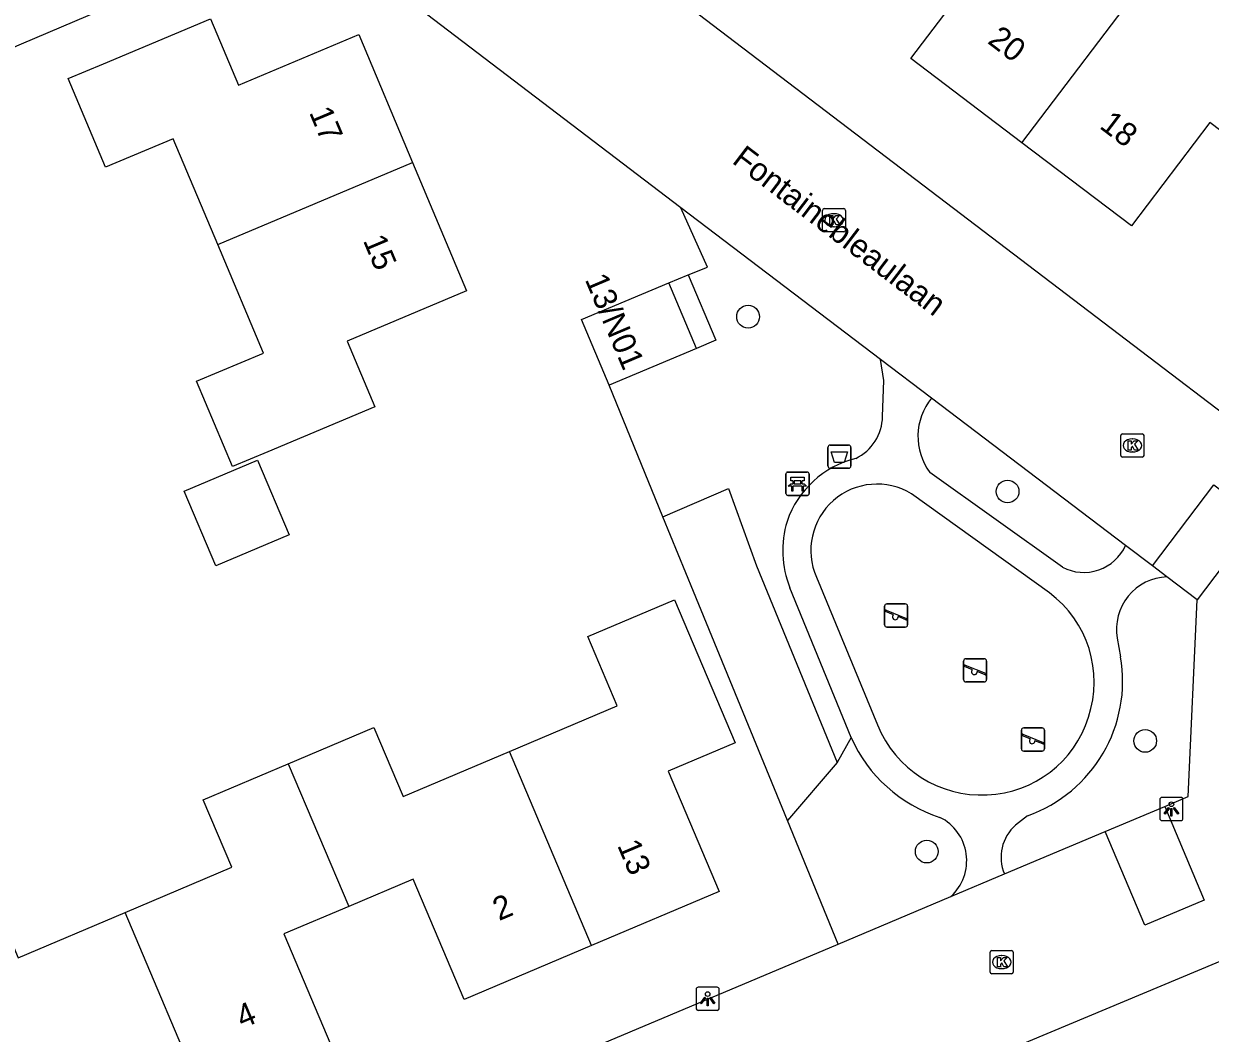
# Model space of a CAD drawing. Extents: x 158474 to 159560, y 388525 to 389605.
# Drawn here: x 158604 to 158655.1, y 389050.1 to 389093.6 of the extents above; entities that cross this region are included whole.
import ezdxf

# ---------------------------------------------------------------- set-up
doc = ezdxf.new("R2010")
doc.units = 0
for name, color, linetype in [('IMGEO_Afvalbak', 7, 'Continuous'), ('IMGEO_Bank', 7, 'Continuous'), ('IMGEO_Boom', 7, 'Continuous'), ('IMGEO_Groenvoorziening', 7, 'Continuous'), ('IMGEO_Kolk', 7, 'Continuous'), ('IMGEO_Lichtpunt', 7, 'Continuous'), ('IMGEO_Openbare_ruimte_label', 7, 'Continuous'), ('IMGEO_Pand', 7, 'Continuous'), ('IMGEO_Pand_nummerreeks', 7, 'Continuous'), ('IMGEO_Rijbaan_lokaal_open', 7, 'Continuous'), ('IMGEO_Speelvoorziening', 7, 'Continuous'), ('IMGEO_Voetpad_open', 7, 'Continuous')]:
    doc.layers.add(name, color=color, linetype=linetype)

msp = doc.modelspace()

# ---------------------------------------------------------------- linework, layer by layer
at = {"layer": 'IMGEO_Afvalbak'}
for p, q in [((158638.613, 389074.52), (158638.613, 389075.32)), ((158638.613, 389075.32), (158638.613, 389074.52)), ((158638.713, 389075.42), (158639.503, 389075.42)), ((158639.503, 389075.42), (158638.713, 389075.42)), ((158639.603, 389075.32), (158639.603, 389074.52)), ((158639.603, 389074.52), (158639.603, 389075.32)), ((158639.503, 389074.42), (158638.713, 389074.42)), ((158638.713, 389074.42), (158639.503, 389074.42))]:
    msp.add_line(p, q, dxfattribs=at)
msp.add_lwpolyline([(158638.756, 389075.134), (158639.46, 389075.134), (158639.311, 389074.664), (158638.905, 389074.664), (158638.756, 389075.134)], dxfattribs=at)
for centre, start, end in [((158638.713, 389075.32), 90, 180), ((158638.713, 389075.32), 90, 180), ((158639.503, 389075.32), 0, 90), ((158639.503, 389075.32), 360, 90), ((158638.713, 389074.52), 180, 270), ((158638.713, 389074.52), 180, 270), ((158639.503, 389074.52), 270, 0), ((158639.503, 389074.52), 270, 0)]:
    msp.add_arc(centre, 0.1, start, end, dxfattribs=at)
at = {"layer": 'IMGEO_Bank'}
for p, q in [((158636.806, 389073.329), (158636.806, 389074.17)), ((158636.806, 389074.17), (158636.806, 389073.329)), ((158636.881, 389074.254), (158637.722, 389074.254)), ((158637.722, 389074.254), (158636.881, 389074.254)), ((158637.806, 389074.179), (158637.806, 389073.338)), ((158637.806, 389073.338), (158637.806, 389074.179)), ((158637.503, 389073.652), (158637.11, 389073.652)), ((158637.115, 389073.76), (158637.115, 389073.866)), ((158637.159, 389073.866), (158637.159, 389073.76)), ((158637.447, 389073.872), (158637.165, 389073.872)), ((158637.165, 389073.754), (158637.447, 389073.754)), ((158637.453, 389073.76), (158637.453, 389073.866)), ((158637.497, 389073.866), (158637.497, 389073.76)), ((158637.731, 389073.254), (158636.89, 389073.254)), ((158636.89, 389073.254), (158637.731, 389073.254))]:
    msp.add_line(p, q, dxfattribs=at)
for points in [[(158637.053, 389073.652), (158636.911, 389073.652), (158637.023, 389073.754), (158637.109, 389073.754)], [(158637.109, 389073.872), (158637.023, 389073.872), (158637.023, 389074.033), (158637.586, 389074.033), (158637.586, 389073.872), (158637.503, 389073.872)], [(158637.103, 389073.645), (158637.103, 389073.438), (158637.06, 389073.438), (158637.06, 389073.645)], [(158637.503, 389073.754), (158637.586, 389073.754), (158637.698, 389073.652), (158637.559, 389073.652)], [(158637.553, 389073.645), (158637.553, 389073.438), (158637.509, 389073.438), (158637.509, 389073.645)]]:
    msp.add_lwpolyline(points, dxfattribs=at)
for centre, radius, start, end in [((158636.884, 389074.176), 0.0779, 92.4484, 184.2845), ((158636.884, 389074.176), 0.0779, 92.4484, 184.2845), ((158637.728, 389074.176), 0.0779, 2.4484, 94.2845), ((158637.728, 389074.176), 0.0779, 2.4484, 94.2845), ((158637.053, 389073.645), 0.00671, 2.8957, 87.1043), ((158637.11, 389073.645), 0.00671, 92.8957, 177.1043), ((158637.108, 389073.865), 0.00671, 2.8957, 87.1043), ((158637.108, 389073.761), 0.00671, 272.8957, 357.1043), ((158637.165, 389073.865), 0.00671, 92.8957, 177.1043), ((158637.165, 389073.761), 0.00671, 182.8957, 267.1043), ((158637.447, 389073.865), 0.00671, 2.8957, 87.1043), ((158637.447, 389073.761), 0.00671, 272.8957, 357.1043), ((158637.504, 389073.865), 0.00671, 92.8957, 177.1043), ((158637.504, 389073.761), 0.00671, 182.8957, 267.1043), ((158637.502, 389073.645), 0.00671, 2.8957, 87.1043), ((158637.559, 389073.645), 0.00671, 92.8957, 177.1043), ((158636.884, 389073.332), 0.0779, 182.4484, 274.2845), ((158636.884, 389073.332), 0.0779, 182.4484, 274.2845), ((158637.728, 389073.332), 0.0779, 272.4484, 4.2845), ((158637.728, 389073.332), 0.0779, 272.4484, 4.2845)]:
    msp.add_arc(centre, radius, start, end, dxfattribs=at)
at = {"layer": 'IMGEO_Boom'}
for centre in [(158635.178, 389080.946), (158646.351, 389073.419), (158652.276, 389062.68), (158642.87, 389057.916)]:
    msp.add_circle(centre, 0.489, dxfattribs=at)
at = {"layer": 'IMGEO_Groenvoorziening'}
for points in [[(158632.597, 389082.746), (158633.427, 389083.084), (158632.28, 389085.631)], [(158631.513, 389072.331), (158629.191, 389077.996)], [(158639.62, 389062.825), (158639.015, 389061.757)], [(158639.056, 389053.929), (158636.872, 389059.257)]]:
    msp.add_lwpolyline(points, dxfattribs=at)
at = {"layer": 'IMGEO_Kolk'}
for p, q in [((158638.377, 389084.673), (158638.377, 389085.525)), ((158638.452, 389085.599), (158639.304, 389085.599)), ((158639.378, 389085.525), (158639.378, 389084.673)), ((158638.865, 389085.379), (158638.89, 389085.379)), ((158639.304, 389084.599), (158638.452, 389084.599)), ((158638.888, 389084.819), (158638.863, 389084.819)), ((158651.223, 389074.976), (158651.223, 389075.828)), ((158651.298, 389075.902), (158652.15, 389075.902)), ((158651.711, 389075.682), (158651.736, 389075.682)), ((158652.224, 389075.828), (158652.224, 389074.976)), ((158652.15, 389074.902), (158651.298, 389074.902)), ((158651.734, 389075.122), (158651.709, 389075.122)), ((158645.597, 389052.73), (158645.597, 389053.582)), ((158645.672, 389053.656), (158646.524, 389053.656)), ((158646.085, 389053.436), (158646.11, 389053.436)), ((158646.598, 389053.582), (158646.598, 389052.73)), ((158646.108, 389052.876), (158646.083, 389052.876)), ((158646.524, 389052.656), (158645.672, 389052.656))]:
    msp.add_line(p, q, dxfattribs=at)
for points in [[(158638.377, 389084.673), (158638.377, 389085.525)], [(158638.452, 389085.599), (158639.304, 389085.599)], [(158639.378, 389085.525), (158639.378, 389084.673)], [(158638.698, 389085.299), (158638.821, 389085.299), (158638.821, 389085.148), (158638.951, 389085.299), (158639.115, 389085.299), (158638.969, 389085.148), (158639.122, 389084.899), (158638.97, 389084.899), (158638.885, 389085.063), (158638.821, 389084.996), (158638.821, 389084.899), (158638.698, 389084.899), (158638.698, 389085.299)], [(158639.304, 389084.599), (158638.452, 389084.599)], [(158651.223, 389074.976), (158651.223, 389075.828)], [(158651.298, 389075.902), (158652.15, 389075.902)], [(158652.224, 389075.828), (158652.224, 389074.976)], [(158651.544, 389075.602), (158651.667, 389075.602), (158651.667, 389075.451), (158651.797, 389075.602), (158651.961, 389075.602), (158651.815, 389075.451), (158651.968, 389075.202), (158651.816, 389075.202), (158651.731, 389075.366), (158651.667, 389075.299), (158651.667, 389075.202), (158651.544, 389075.202), (158651.544, 389075.602)], [(158652.15, 389074.902), (158651.298, 389074.902)], [(158645.597, 389052.73), (158645.597, 389053.582)], [(158645.672, 389053.656), (158646.524, 389053.656)], [(158645.918, 389053.356), (158646.041, 389053.356), (158646.041, 389053.205), (158646.171, 389053.356), (158646.335, 389053.356), (158646.189, 389053.205), (158646.342, 389052.956), (158646.19, 389052.956), (158646.105, 389053.12), (158646.041, 389053.053), (158646.041, 389052.956), (158645.918, 389052.956), (158645.918, 389053.356)], [(158646.598, 389053.582), (158646.598, 389052.73)], [(158646.524, 389052.656), (158645.672, 389052.656)]]:
    msp.add_lwpolyline(points, dxfattribs=at)
for centre, start, end in [((158638.454, 389085.523), 91.552, 178.448), ((158638.454, 389085.523), 91.552, 178.448), ((158639.302, 389085.523), 1.552, 88.448), ((158639.302, 389085.523), 1.552, 88.448), ((158638.454, 389084.675), 181.552, 268.448), ((158638.454, 389084.675), 181.552, 268.448), ((158639.302, 389084.675), 271.552, 358.448), ((158639.302, 389084.675), 271.552, 358.448), ((158651.3, 389075.826), 91.552, 178.448), ((158651.3, 389075.826), 91.552, 178.448), ((158652.148, 389075.826), 1.552, 88.448), ((158652.148, 389075.826), 1.552, 88.448), ((158651.3, 389074.978), 181.552, 268.448), ((158651.3, 389074.978), 181.552, 268.448), ((158652.148, 389074.978), 271.552, 358.448), ((158652.148, 389074.978), 271.552, 358.448), ((158645.674, 389053.58), 91.552, 178.448), ((158645.674, 389053.58), 91.552, 178.448), ((158646.522, 389053.58), 1.552, 88.448), ((158646.522, 389053.58), 1.552, 88.448), ((158645.674, 389052.732), 181.552, 268.448), ((158645.674, 389052.732), 181.552, 268.448), ((158646.522, 389052.732), 271.552, 358.448), ((158646.522, 389052.732), 271.552, 358.448)]:
    msp.add_arc(centre, 0.0765, start, end, dxfattribs=at)
for centre, major_axis, ratio, start_param, end_param in [((158638.864, 389085.099), (-0.387, 0.002), 0.722429, 4.712389, 7.853982), ((158638.889, 389085.099), (-0.39, 0.002), 0.717154, 1.570796, 4.712389), ((158651.71, 389075.402), (-0.387, 0.002), 0.722429, 4.712389, 7.853982), ((158651.735, 389075.402), (-0.39, 0.002), 0.717154, 1.570796, 4.712389), ((158646.084, 389053.156), (-0.387, 0.002), 0.722429, 4.712389, 7.853982), ((158646.109, 389053.156), (-0.39, 0.002), 0.717154, 1.570796, 4.712389)]:
    msp.add_ellipse(centre, major_axis=major_axis, ratio=ratio, start_param=start_param, end_param=end_param, dxfattribs=at)
at = {"layer": 'IMGEO_Lichtpunt'}
for p, q in [((158652.906, 389060.153), (158652.906, 389059.346)), ((158652.906, 389060.153), (158652.906, 389059.346)), ((158653.808, 389060.248), (158653, 389060.248)), ((158653.808, 389060.248), (158653, 389060.248)), ((158653.902, 389059.346), (158653.902, 389060.153)), ((158653.902, 389059.346), (158653.902, 389060.153)), ((158653, 389059.252), (158653.808, 389059.252)), ((158653, 389059.252), (158653.808, 389059.252)), ((158632.939, 389051.981), (158632.939, 389051.174)), ((158632.939, 389051.981), (158632.939, 389051.174)), ((158633.841, 389052.076), (158633.033, 389052.076)), ((158633.841, 389052.076), (158633.033, 389052.076)), ((158633.935, 389051.174), (158633.935, 389051.981)), ((158633.935, 389051.174), (158633.935, 389051.981)), ((158633.033, 389051.08), (158633.841, 389051.08)), ((158633.033, 389051.08), (158633.841, 389051.08))]:
    msp.add_line(p, q, dxfattribs=at)
for points in [[(158653.28, 389059.817), (158653.319, 389059.789), (158653.131, 389059.527), (158653.093, 389059.554), (158653.28, 389059.817)], [(158653.382, 389059.769), (158653.429, 389059.769), (158653.429, 389059.447), (158653.382, 389059.447), (158653.382, 389059.769)], [(158653.492, 389059.789), (158653.53, 389059.816), (158653.717, 389059.554), (158653.678, 389059.526), (158653.492, 389059.789)], [(158633.313, 389051.645), (158633.352, 389051.617), (158633.164, 389051.355), (158633.126, 389051.382), (158633.313, 389051.645)], [(158633.415, 389051.597), (158633.462, 389051.597), (158633.462, 389051.275), (158633.415, 389051.275), (158633.415, 389051.597)], [(158633.525, 389051.617), (158633.563, 389051.644), (158633.75, 389051.382), (158633.711, 389051.354), (158633.525, 389051.617)]]:
    msp.add_lwpolyline(points, dxfattribs=at)
for centre in [(158653.405, 389059.951), (158633.438, 389051.779)]:
    msp.add_circle(centre, 0.0994, dxfattribs=at)
for centre, start, end in [((158653, 389060.153), 90, 180), ((158653, 389060.153), 90, 180), ((158653.808, 389060.153), 0, 90), ((158653.808, 389060.153), 0, 90), ((158653, 389059.346), 180, 270), ((158653, 389059.346), 180, 270), ((158653.808, 389059.346), 270, 0), ((158653.808, 389059.346), 270, 360), ((158633.033, 389051.981), 90, 180), ((158633.033, 389051.981), 90, 180), ((158633.841, 389051.981), 0, 90), ((158633.841, 389051.981), 0, 90), ((158633.033, 389051.174), 180, 270), ((158633.033, 389051.174), 180, 270), ((158633.841, 389051.174), 270, 0), ((158633.841, 389051.174), 270, 360)]:
    msp.add_arc(centre, 0.0946, start, end, dxfattribs=at)
at = {"layer": 'IMGEO_Pand'}
for points in [[(158599.882, 389100.941), (158601.096, 389098.116), (158606.137, 389100.282), (158608.471, 389094.647), (158603.878, 389092.674), (158600.199, 389091.093), (158598.161, 389095.835), (158595.246, 389094.582), (158593.662, 389098.268)], [(158646.967, 389088.432), (158642.186, 389092.061), (158645.576, 389096.527), (158643.223, 389098.313)], [(158646.967, 389088.432), (158652.463, 389095.674)], [(158612.351, 389084.052), (158610.433, 389088.608), (158607.514, 389087.379), (158605.907, 389091.198), (158607.427, 389091.838), (158612.035, 389093.777), (158613.24, 389090.914), (158618.415, 389093.093), (158620.735, 389087.58)], [(158657.482, 389087.472), (158655.063, 389089.308), (158651.682, 389084.853), (158646.967, 389088.432)], [(158620.735, 389087.58), (158623.057, 389082.064), (158617.913, 389079.898), (158619.105, 389077.067), (158614.497, 389075.127), (158612.984, 389074.49), (158611.436, 389078.167), (158614.318, 389079.38), (158612.351, 389084.052)], [(158612.351, 389084.052), (158620.735, 389087.58)], [(158629.191, 389077.996), (158628.001, 389080.824), (158631.763, 389082.407)], [(158632.954, 389079.579), (158631.763, 389082.407)], [(158632.954, 389079.579), (158629.191, 389077.996)], [(158610.906, 389073.436), (158614.06, 389074.764), (158615.414, 389071.548), (158612.26, 389070.22), (158610.906, 389073.436)], [(158624.9, 389062.228), (158629.541, 389064.194), (158628.276, 389067.181), (158632.007, 389068.761), (158634.617, 389062.599), (158631.741, 389061.38), (158633.937, 389056.198), (158628.441, 389053.87)], [(158615.382, 389061.7), (158619.069, 389063.262), (158620.328, 389060.291), (158624.9, 389062.228)], [(158628.441, 389053.87), (158624.9, 389062.228)], [(158608.356, 389055.289), (158612.953, 389057.237), (158611.719, 389060.148), (158615.382, 389061.7)], [(158615.382, 389061.7), (158617.987, 389055.55)], [(158598.842, 389054.75), (158602.499, 389056.3), (158603.753, 389053.339), (158608.356, 389055.289)], [(158628.441, 389053.87), (158622.949, 389051.543), (158620.755, 389056.723), (158617.987, 389055.55)], [(158611.905, 389046.91), (158608.356, 389055.289)], [(158617.987, 389055.55), (158615.197, 389054.368), (158617.375, 389049.227), (158611.905, 389046.91)]]:
    msp.add_lwpolyline(points, dxfattribs=at)
at = {"layer": 'IMGEO_Rijbaan_lokaal_open'}
for points in [[(158601.848, 389145.539), (158600.426, 389141.831), (158604.336, 389132.54), (158605.841, 389128.964), (158616.4, 389103.871), (158618.796, 389104.84), (158666.009, 389068.886)], [(158632.28, 389085.631), (158618.202, 389096.374), (158612.964, 389094.303), (158598.129, 389129.848)], [(158640.886, 389079.099), (158632.28, 389085.631)], [(158643.071, 389077.441), (158640.886, 389079.099)], [(158651.434, 389071.094), (158643.071, 389077.441)], [(158652.585, 389070.22), (158655.228, 389073.702), (158657.155, 389072.238), (158654.513, 389068.757)], [(158652.585, 389070.22), (158651.434, 389071.094)], [(158653.212, 389069.744), (158652.585, 389070.22)], [(158654.513, 389068.757), (158653.212, 389069.744)], [(158653.115, 389059.863), (158654.128, 389060.291), (158654.513, 389068.757)], [(158650.554, 389058.782), (158653.115, 389059.863)], [(158653.115, 389059.863), (158654.819, 389055.829), (158652.258, 389054.748), (158650.554, 389058.782)], [(158693.979, 389034.415), (158691.297, 389040.872), (158689.958, 389044.098), (158688.082, 389043.319), (158668.118, 389058.458), (158641.722, 389047.425), (158602.187, 389030.899), (158601.851, 389031.612), (158596.34, 389029.317)], [(158646.219, 389056.952), (158650.554, 389058.782)], [(158643.914, 389055.983), (158646.219, 389056.952)], [(158639.056, 389053.929), (158643.914, 389055.983)], [(158594.001, 389034.936), (158639.056, 389053.929)]]:
    msp.add_lwpolyline(points, dxfattribs=at)
at = {"layer": 'IMGEO_Speelvoorziening'}
for p, q in [((158641.156, 389068.581), (158641.946, 389068.581)), ((158641.946, 389068.581), (158641.156, 389068.581)), ((158641.056, 389067.681), (158641.056, 389068.481)), ((158641.056, 389068.481), (158641.056, 389067.681)), ((158641.439, 389068.109), (158641.1, 389068.246)), ((158641.125, 389068.306), (158642.001, 389067.953)), ((158641.977, 389067.893), (158641.637, 389068.03)), ((158642.046, 389068.481), (158642.046, 389067.681)), ((158642.046, 389067.681), (158642.046, 389068.481)), ((158641.946, 389067.581), (158641.156, 389067.581)), ((158641.156, 389067.581), (158641.946, 389067.581)), ((158644.459, 389065.319), (158644.459, 389066.119)), ((158644.459, 389066.119), (158644.459, 389065.319)), ((158644.559, 389066.219), (158645.349, 389066.219)), ((158645.349, 389066.219), (158644.559, 389066.219)), ((158645.449, 389066.119), (158645.449, 389065.319)), ((158645.449, 389065.319), (158645.449, 389066.119)), ((158644.842, 389065.747), (158644.503, 389065.884)), ((158644.528, 389065.944), (158645.404, 389065.591)), ((158645.38, 389065.531), (158645.04, 389065.668)), ((158645.349, 389065.219), (158644.559, 389065.219)), ((158644.559, 389065.219), (158645.349, 389065.219)), ((158646.945, 389062.34), (158646.945, 389063.14)), ((158646.945, 389063.14), (158646.945, 389062.34)), ((158647.014, 389062.965), (158647.89, 389062.612)), ((158647.045, 389063.24), (158647.835, 389063.24)), ((158647.835, 389063.24), (158647.045, 389063.24)), ((158647.935, 389063.14), (158647.935, 389062.34)), ((158647.935, 389062.34), (158647.935, 389063.14)), ((158647.328, 389062.768), (158646.989, 389062.905)), ((158647.866, 389062.552), (158647.526, 389062.689)), ((158647.835, 389062.24), (158647.045, 389062.24)), ((158647.045, 389062.24), (158647.835, 389062.24))]:
    msp.add_line(p, q, dxfattribs=at)
for centre, radius, start, end in [((158641.156, 389068.481), 0.1, 90, 180), ((158641.156, 389068.481), 0.1, 90, 180), ((158641.946, 389068.481), 0.1, 0, 90), ((158641.946, 389068.481), 0.1, 360, 90), ((158641.113, 389068.276), 0.0327, 68.078, 248.078), ((158641.518, 389068.019), 0.12, 130.9928, 5.1632), ((158641.156, 389067.681), 0.1, 180, 270), ((158641.156, 389067.681), 0.1, 180, 270), ((158641.946, 389067.681), 0.1, 270, 0), ((158641.946, 389067.681), 0.1, 270, 0), ((158641.989, 389067.923), 0.0327, 248.078, 68.078), ((158644.559, 389066.119), 0.1, 90, 180), ((158644.559, 389066.119), 0.1, 90, 180), ((158645.349, 389066.119), 0.1, 0, 90), ((158645.349, 389066.119), 0.1, 360, 90), ((158644.516, 389065.914), 0.0327, 68.078, 248.078), ((158644.921, 389065.657), 0.12, 130.9928, 5.1632), ((158645.392, 389065.561), 0.0327, 248.078, 68.078), ((158644.559, 389065.319), 0.1, 180, 270), ((158644.559, 389065.319), 0.1, 180, 270), ((158645.349, 389065.319), 0.1, 270, 0), ((158645.349, 389065.319), 0.1, 270, 0), ((158647.045, 389063.14), 0.1, 90, 180), ((158647.045, 389063.14), 0.1, 90, 180), ((158647.002, 389062.935), 0.0327, 68.078, 248.078), ((158647.835, 389063.14), 0.1, 0, 90), ((158647.835, 389063.14), 0.1, 360, 90), ((158647.407, 389062.678), 0.12, 130.9928, 5.1632), ((158647.878, 389062.582), 0.0327, 248.078, 68.078), ((158647.045, 389062.34), 0.1, 180, 270), ((158647.045, 389062.34), 0.1, 180, 270), ((158647.835, 389062.34), 0.1, 270, 0), ((158647.835, 389062.34), 0.1, 270, 0)]:
    msp.add_arc(centre, radius, start, end, dxfattribs=at)
at = {"layer": 'IMGEO_Voetpad_open'}
for points in [[(158631.763, 389082.407), (158632.597, 389082.746)], [(158632.597, 389082.746), (158633.783, 389079.928), (158632.954, 389079.579)], [(158640.968, 389076.65), (158641.016, 389078.203), (158640.886, 389079.099)], [(158648.71, 389070.161), (158642.999, 389074.235)], [(158631.513, 389072.331), (158634.33, 389073.555), (158635.545, 389070.223), (158639.015, 389061.757)], [(158648.149, 389069.059), (158642.217, 389073.321)], [(158636.872, 389059.257), (158632.833, 389069.111), (158631.513, 389072.331)], [(158638.123, 389069.732), (158640.749, 389063.37)], [(158639.62, 389062.825), (158636.981, 389069.277)], [(158651.074, 389067.108), (158651.214, 389066.305)], [(158639.015, 389061.757), (158636.872, 389059.257)], [(158647.207, 389059.46), (158646.692, 389059.056)]]:
    msp.add_lwpolyline(points, dxfattribs=at)
for centre, radius, start, end in [((158645.13, 389075.791), 2.638, 141.2872, 216.1398), ((158638.92, 389076.685), 2.048, 295.819, 359.0216), ((158640.819, 389070.772), 4.192, 103.9054, 161.04), ((158640.731, 389070.886), 2.852, 58.6078, 203.871), ((158640.995, 389070.885), 4.325, 163.2178, 201.8327), ((158649.629, 389071.922), 1.986, 242.4582, 335.3556), ((158653.292, 389067.494), 2.251, 92.0247, 189.8859), ((158645.29, 389065.216), 4.79, 341.5729, 53.3482), ((158645.161, 389065.253), 6.144, 289.4506, 9.8608), ((158645.295, 389065.108), 4.752, 272.0997, 342.7947), ((158645.213, 389065.163), 4.81, 201.8791, 273.0513), ((158645.367, 389065.371), 6.286, 203.895, 252.119), ((158642.504, 389057.522), 2.087, 312.5011, 63.4434), ((158647.9, 389057.679), 1.831, 131.2625, 203.3975)]:
    msp.add_arc(centre, radius, start, end, dxfattribs=at)

# ---------------------------------------------------------------- texts
at = {"layer": 'IMGEO_Openbare_ruimte_label'}
msp.add_text('Fontainebleaulaan', height=1, rotation=322.7177, dxfattribs=at).set_placement((158634.445, 389087.59))
at = {"layer": 'IMGEO_Pand_nummerreeks'}
for s, rotation, p in [('20', 322.7994, (158645.445, 389092.751)), ('17', 292.8225, (158616.267, 389089.743)), ('18', 322.7994, (158650.265, 389089.092)), ('15', 292.829, (158618.588, 389084.228)), ('13/N01', 292.9566, (158628.14, 389082.55)), ('13', 292.966, (158629.532, 389058.185)), ('2', 22.9842, (158624.455, 389054.919)), ('4', 22.9593, (158613.404, 389050.282))]:
    msp.add_text(s, height=1, rotation=rotation, dxfattribs=at).set_placement(p)

doc.saveas('drawing.dxf')
